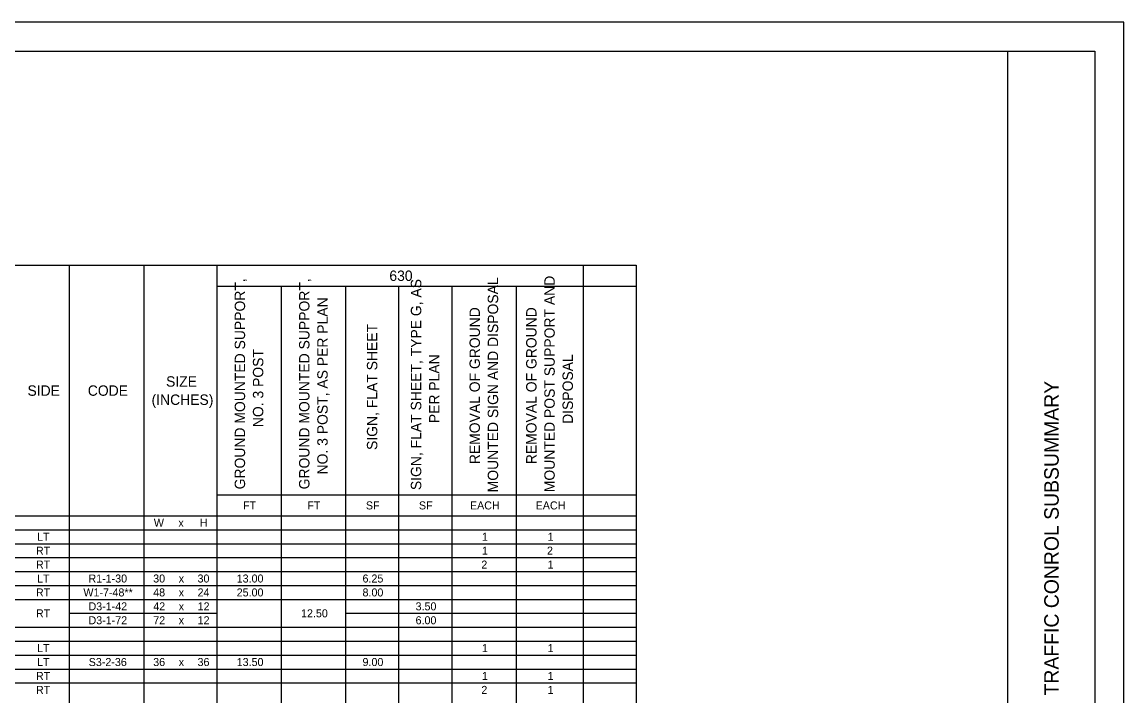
# Model space of a CAD drawing. Extents: x 0 to 35.9, y 0 to 22.
# Drawn here: x 15 to 34, y 10.38 to 22 of the extents above; entities that cross this region are included whole.
import ezdxf

# ---------------------------------------------------------------- set-up
doc = ezdxf.new("R2010")
doc.units = 0
for name, color, linetype in [('SH_Border', 7, 'Continuous'), ('SH_Cut_Line', 7, 'Continuous'), ('SH_Data', 7, 'Continuous'), ('SH_Text', 7, 'Continuous')]:
    doc.layers.add(name, color=color, linetype=linetype)

msp = doc.modelspace()

# ---------------------------------------------------------------- linework, layer by layer
at = {"layer": 'SH_Border'}
msp.add_line((32, 0.5), (32, 21.5), dxfattribs=at)
msp.add_lwpolyline([(1.5, 21.5), (33.5, 21.5), (33.5, 0.5), (1.5, 0.5)], close=True, dxfattribs=at)
at = {"layer": 'SH_Cut_Line'}
msp.add_lwpolyline([(0, 0), (34, 0), (34, 22), (0, 22)], close=True, dxfattribs=at)
at = {"layer": 'SH_Text'}
for p, q in [((7.706, 17.807), (25.586, 17.807)), ((15.806, 17.807), (15.806, 4.847)), ((17.096, 17.807), (17.096, 3.992)), ((18.356, 17.807), (18.356, 3.992)), ((24.671, 17.807), (24.671, 3.992)), ((25.586, 17.807), (25.586, 3.992)), ((18.356, 17.447), (25.586, 17.447)), ((19.466, 17.447), (19.466, 3.992)), ((20.576, 17.447), (20.576, 3.992)), ((21.491, 17.447), (21.491, 3.992)), ((22.406, 17.447), (22.406, 3.992)), ((23.516, 17.447), (23.516, 3.992)), ((18.356, 13.847), (25.586, 13.847)), ((7.706, 13.487), (25.586, 13.487)), ((7.706, 13.247), (25.586, 13.247)), ((7.706, 13.007), (25.586, 13.007)), ((7.706, 12.767), (25.586, 12.767)), ((7.706, 12.527), (25.586, 12.527)), ((7.706, 12.287), (25.586, 12.287)), ((7.706, 12.047), (25.586, 12.047)), ((15.806, 11.807), (18.356, 11.807)), ((20.576, 11.807), (25.586, 11.807)), ((7.706, 11.567), (25.586, 11.567)), ((7.706, 11.327), (25.586, 11.327)), ((7.706, 11.087), (25.586, 11.087)), ((7.706, 10.847), (25.586, 10.847)), ((7.706, 10.607), (25.586, 10.607))]:
    msp.add_line(p, q, dxfattribs=at)

# ---------------------------------------------------------------- texts
at = {"layer": 'SH_Data'}
msp.add_text('TRAFFIC CONROL SUBSUMMARY', height=0.25, rotation=90, dxfattribs=at).set_placement((32.875, 10.391))
at = {"layer": 'SH_Text'}
for s, height, p in [('630', 0.1794, (21.331, 17.537)), ('SIZE ', 0.1794, (17.48, 15.714)), ('SIDE', 0.1794, (15.09, 15.557)), ('CODE', 0.1794, (16.13, 15.557)), ('(INCHES)', 0.1794, (17.23, 15.4)), ('FT', 0.138, (18.806, 13.598)), ('FT', 0.138, (19.916, 13.598)), ('SF', 0.138, (20.926, 13.598)), ('SF', 0.138, (21.841, 13.598)), ('EACH', 0.138, (22.721, 13.598)), ('EACH', 0.138, (23.854, 13.598)), ('W', 0.138, (17.269, 13.298)), ('x', 0.138, (17.693, 13.298)), ('H', 0.138, (18.06, 13.298)), ('LT', 0.138, (15.255, 13.058)), ('1', 0.138, (22.928, 13.058)), ('1', 0.138, (24.061, 13.058)), ('RT', 0.138, (15.236, 12.818)), ('1', 0.138, (22.928, 12.818)), ('2', 0.138, (24.049, 12.818)), ('RT', 0.138, (15.236, 12.578)), ('2', 0.138, (22.917, 12.578)), ('1', 0.138, (24.061, 12.578)), ('LT', 0.138, (15.255, 12.338)), ('R1-1-30', 0.138, (16.141, 12.338)), ('30', 0.138, (17.258, 12.338)), ('x', 0.138, (17.698, 12.338)), ('30', 0.138, (18.023, 12.338)), ('13.00', 0.138, (18.698, 12.338)), ('6.25', 0.138, (20.868, 12.338)), ('RT', 0.138, (15.236, 12.098)), ('W1-7-48**', 0.138, (16.054, 12.098)), ('48', 0.138, (17.258, 12.098)), ('x', 0.138, (17.698, 12.098)), ('24', 0.138, (18.023, 12.098)), ('25.00', 0.138, (18.698, 12.098)), ('8.00', 0.138, (20.868, 12.098)), ('D3-1-42', 0.138, (16.142, 11.858)), ('42', 0.138, (17.259, 11.858)), ('12', 0.138, (18.024, 11.858)), ('3.50', 0.138, (21.783, 11.858)), ('RT', 0.138, (15.236, 11.738)), ('x', 0.138, (17.698, 11.858)), ('12.50', 0.138, (19.808, 11.738)), ('D3-1-72', 0.138, (16.142, 11.618)), ('72', 0.138, (17.259, 11.618)), ('x', 0.138, (17.698, 11.618)), ('12', 0.138, (18.024, 11.618)), ('6.00', 0.138, (21.783, 11.618)), ('LT', 0.138, (15.255, 11.138)), ('1', 0.138, (22.928, 11.138)), ('1', 0.138, (24.061, 11.138)), ('LT', 0.138, (15.255, 10.898)), ('S3-2-36', 0.138, (16.146, 10.898)), ('36', 0.138, (17.258, 10.898)), ('36', 0.138, (18.023, 10.898)), ('13.50', 0.138, (18.698, 10.898)), ('9.00', 0.138, (20.868, 10.898)), ('x', 0.138, (17.698, 10.898)), ('RT', 0.138, (15.236, 10.658)), ('1', 0.138, (22.928, 10.658)), ('1', 0.138, (24.061, 10.658)), ('RT', 0.138, (15.236, 10.418)), ('2', 0.138, (22.917, 10.418)), ('1', 0.138, (24.061, 10.418))]:
    msp.add_text(s, height=height, dxfattribs=at).set_placement(p)
for s, p in [('GROUND MOUNTED SUPPORT, ', (18.843, 13.944)), ('GROUND MOUNTED SUPPORT, ', (19.953, 13.944)), ('SIGN, FLAT SHEET, TYPE G, AS ', (21.881, 13.931)), ('MOUNTED SIGN AND DISPOSAL', (23.207, 13.893)), ('MOUNTED POST SUPPORT AND ', (24.183, 13.895)), ('NO. 3 POST, AS PER PLAN', (20.267, 14.201)), ('REMOVAL OF GROUND ', (22.893, 14.378)), ('REMOVAL OF GROUND ', (23.869, 14.378)), ('SIGN, FLAT SHEET', (21.123, 14.623)), ('NO. 3 POST', (19.157, 15.016)), ('PER PLAN', (22.195, 15.085)), ('DISPOSAL', (24.497, 15.073))]:
    msp.add_text(s, height=0.1794, rotation=90, dxfattribs=at).set_placement(p)

doc.saveas('drawing.dxf')
